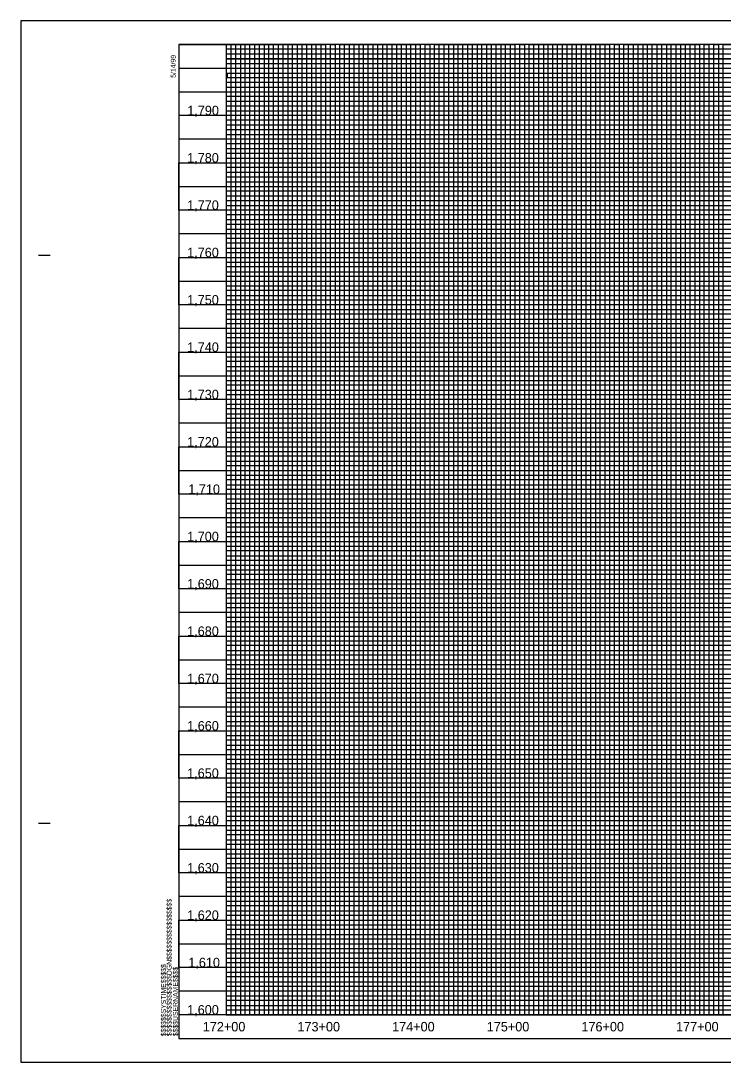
# Model space of a CAD drawing. Extents: x 505602 to 507286, y 483109 to 484209.
# Drawn here: x 505602 to 506344, y 483109 to 484209 of the extents above; entities that cross this region are included whole.
import ezdxf

# ---------------------------------------------------------------- set-up
doc = ezdxf.new("R2010")
doc.units = 0
for name, color, linetype in [('Exist Vertical Profile Vertical Axis Label', 7, 'Continuous'), ('Sheet Layout Profile Border Port 1', 7, 'Continuous'), ('Sheet Plot Border Outside CELL', 7, 'Continuous'), ('Sheet Profile CELL', 7, 'Continuous'), ('Sheet Profile Grid Major CELL', 7, 'Continuous'), ('Sheet Profile Grid Middle CELL', 7, 'Continuous'), ('Sheet Profile Grid Minor CELL', 7, 'Continuous')]:
    doc.layers.add(name, color=color, linetype=linetype)

msp = doc.modelspace()

# ---------------------------------------------------------------- linework, layer by layer
at = {"layer": 'Sheet Layout Profile Border Port 1'}
msp.add_lwpolyline([(505819.1, 484183.7), (505819.1, 483158.7), (507219.1, 483158.7), (507219.1, 484022.7), (507069, 484022.7), (507069, 484183.7)], close=True, dxfattribs=at)
at = {"layer": 'Sheet Plot Border Outside CELL'}
msp.add_lwpolyline([(507286.1, 484208.7), (505602.1, 484208.7), (505602.1, 483108.7), (507286.1, 483108.7)], close=True, dxfattribs=at)
at = {"layer": 'Sheet Profile CELL'}
for p, q in [((505620.6, 483961.2), (505633.1, 483961.2)), ((505620.6, 483361.2), (505633.1, 483361.2)), ((507269.1, 483158.7), (505769.1, 483158.7)), ((505769.1, 483133.7), (505769.1, 483133.7)), ((505769.1, 483133.7), (505769.1, 483133.7)), ((505769.1, 483133.7), (505769.1, 483133.7)), ((505769.1, 483133.7), (505769.1, 483133.7)), ((505769.1, 483133.7), (505769.1, 483133.7)), ((505769.1, 483133.7), (505769.1, 483133.7))]:
    msp.add_line(p, q, dxfattribs=at)
msp.add_lwpolyline([(507269.1, 484183.7), (505769.1, 484183.7), (505769.1, 483133.7), (507269.1, 483133.7)], close=True, dxfattribs=at)
msp.add_lwpolyline([(505806.6, 483133.7), (505806.6, 483133.7)], dxfattribs=at)
msp.add_lwpolyline([(505806.6, 483133.7), (505806.6, 483133.7)], dxfattribs=at)
at = {"layer": 'Sheet Profile Grid Major CELL'}
for points in [[(505769.1, 484183.7), (505819.1, 484183.7), (505819.1, 483158.7), (505869.1, 483158.7), (505869.1, 484183.7), (505919.1, 484183.7), (505919.1, 483158.7), (505969.1, 483158.7), (505969.1, 484183.7), (506019.1, 484183.7), (506019.1, 483158.7), (506069.1, 483158.7), (506069.1, 484183.7), (506119.1, 484183.7), (506119.1, 483158.7), (506169.1, 483158.7), (506169.1, 484183.7), (506219.1, 484183.7), (506219.1, 483158.7), (506269.1, 483158.7), (506269.1, 484183.7), (506319.1, 484183.7), (506319.1, 483158.7), (506369.1, 483158.7)], [(507069, 484108.7), (505769.2, 484108.7), (505769.2, 484158.7), (507069, 484158.7)], [(507269.1, 484008.7), (505769.1, 484008.7), (505769.1, 484058.7), (507069, 484058.7)], [(507269.1, 483908.7), (505769.1, 483908.7), (505769.1, 483958.7), (507269.1, 483958.7)], [(507269.1, 483808.7), (505769.1, 483808.7), (505769.1, 483858.7), (507269.1, 483858.7)], [(507269.1, 483708.7), (505769.1, 483708.7), (505769.1, 483758.7), (507269.1, 483758.7)], [(507269.1, 483608.7), (505769.1, 483608.7), (505769.1, 483658.7), (507269.1, 483658.7)], [(507269.1, 483508.7), (505769.1, 483508.7), (505769.1, 483558.7), (507269.1, 483558.7)], [(507269.1, 483408.7), (505769.1, 483408.7), (505769.1, 483458.7), (507269.1, 483458.7)], [(507269.1, 483308.7), (505769.1, 483308.7), (505769.1, 483358.7), (507269.1, 483358.7)], [(507269.1, 483208.7), (505769.1, 483208.7), (505769.1, 483258.7), (507269.1, 483258.7)]]:
    msp.add_lwpolyline(points, dxfattribs=at)
at = {"layer": 'Sheet Profile Grid Middle CELL'}
for points in [[(505844.1, 483158.7), (505844.1, 484183.7), (505894.1, 484183.7), (505894.1, 483158.7), (505944.1, 483158.7), (505944.1, 484183.7), (505994.1, 484183.7), (505994.1, 483158.7), (506044.1, 483158.7), (506044.1, 484183.7), (506094.1, 484183.7), (506094.1, 483158.7), (506144.1, 483158.7), (506144.1, 484183.7), (506194.1, 484183.7), (506194.1, 483158.7), (506244.1, 483158.7), (506244.1, 484183.7), (506294.1, 484183.7), (506294.1, 483158.7), (506344.1, 483158.7), (506344.1, 484183.7), (506394.1, 484183.7)], [(505769.1, 484133.7), (507069, 484133.7)], [(507069, 484083.7), (505769.1, 484083.7), (505769.1, 484033.7), (507069, 484033.7)], [(507269.1, 483983.7), (505769.1, 483983.7), (505769.1, 483933.7), (507269.1, 483933.7)], [(507269.1, 483883.7), (505769.1, 483883.7), (505769.1, 483833.7), (507269.1, 483833.7)], [(507269.1, 483783.7), (505769.1, 483783.7), (505769.1, 483733.7), (507269.1, 483733.7)], [(507269.1, 483683.7), (505769.1, 483683.7), (505769.1, 483633.7), (507269.1, 483633.7)], [(507269.1, 483583.7), (505769.1, 483583.7), (505769.1, 483533.7), (507269.1, 483533.7)], [(507269.1, 483483.7), (505769.1, 483483.7), (505769.1, 483433.7), (507269.1, 483433.7)], [(507269.1, 483383.7), (505769.1, 483383.7), (505769.1, 483333.7), (507269.1, 483333.7)], [(507269.1, 483283.7), (505769.1, 483283.7), (505769.1, 483233.7), (507269.1, 483233.7)], [(507269.1, 483183.7), (505769.1, 483183.7)]]:
    msp.add_lwpolyline(points, dxfattribs=at)
at = {"layer": 'Sheet Profile Grid Minor CELL'}
for p, q in [((505819.1, 484168.7), (507069.1, 484168.7)), ((507219.1, 484003.7), (505819.1, 484003.7)), ((505819.1, 484003.7), (505819.1, 483998.7)), ((505819.1, 483998.7), (507219.1, 483998.7)), ((507219.1, 483978.7), (505819.1, 483978.7))]:
    msp.add_line(p, q, dxfattribs=at)
for points in [[(505824.1, 484183.7), (505829.1, 484183.7), (505834.1, 484183.7), (505839.1, 484183.7), (505849.1, 484183.7), (505816, 484183.7), (505821, 484183.7), (505779.1, 484183.7), (505784.1, 484183.7), (505789.1, 484183.7), (505799.1, 484183.7), (505804.1, 484183.7), (505809.1, 484183.7), (505814.1, 484183.7), (505824.1, 484183.7), (505824.1, 483158.7), (505829.1, 483158.7), (505829.1, 484183.7), (505834.1, 484183.7), (505834.1, 483158.7), (505839.1, 483158.7), (505839.1, 484183.7), (505849.1, 484183.7), (505849.1, 483158.7), (505854.1, 483158.7), (505854.1, 484183.7), (505859.1, 484183.7), (505859.1, 483158.7), (505864.1, 483158.7), (505864.1, 484183.7), (505874.1, 484183.7), (505874.1, 483158.7), (505879.1, 483158.7), (505879.1, 484183.7), (505884.1, 484183.7), (505884.1, 483158.7), (505889.1, 483158.7), (505889.1, 484183.7), (505899.1, 484183.7), (505899.1, 483158.7), (505904.1, 483158.7), (505904.1, 484183.7), (505909.1, 484183.7), (505909.1, 483158.7), (505914.1, 483158.7), (505914.1, 484183.7), (505924.1, 484183.7), (505924.1, 483158.7), (505929.1, 483158.7), (505929.1, 484183.7), (505934.1, 484183.7), (505934.1, 483158.7), (505939.1, 483158.7), (505939.1, 484183.7), (505949.1, 484183.7), (505949.1, 483158.7), (505954.1, 483158.7), (505954.1, 484183.7), (505959.1, 484183.7), (505959.1, 483158.7), (505964.1, 483158.7), (505964.1, 484183.7), (505974.1, 484183.7), (505974.1, 483158.7), (505979.1, 483158.7), (505979.1, 484183.7), (505984.1, 484183.7), (505984.1, 483158.7)], [(507069, 484178.7), (505819.1, 484178.7), (505819.1, 484173.7), (507069, 484173.7)], [(505984.1, 483158.7), (505989.1, 483158.7), (505989.1, 484183.7), (505999.1, 484183.7), (505999.1, 483158.7), (506004.1, 483158.7), (506004.1, 484183.7), (506009.1, 484183.7), (506009.1, 483158.7), (506014.1, 483158.7), (506014.1, 484183.7), (506024.1, 484183.7), (506024.1, 483158.7), (506029.1, 483158.7), (506029.1, 484183.7), (506029.1, 484183.7), (506034.1, 484183.7), (506034.1, 483158.7), (506039.1, 483158.7), (506039.1, 484183.7), (506049.1, 484183.7), (506049.1, 483158.7), (506054.1, 483158.7), (506054.1, 484183.7), (506059.1, 484183.7), (506059.1, 483158.7), (506064.1, 483158.7), (506064.1, 484183.7), (506074.1, 484183.7), (506074.1, 483158.7), (506079.1, 483158.7), (506079.1, 484183.7), (506084.1, 484183.7), (506084.1, 483158.7), (506089.1, 483158.7), (506089.1, 484183.7), (506099.1, 484183.7), (506099.1, 483158.7), (506104.1, 483158.7), (506104.1, 484183.7), (506109.1, 484183.7), (506109.1, 483158.7), (506114.1, 483158.7), (506114.1, 484183.7), (506124.1, 484183.7), (506124.1, 483158.7), (506129.1, 483158.7), (506129.1, 484183.7), (506134.1, 484183.7), (506134.1, 483158.7), (506139.1, 483158.7), (506139.1, 484183.7), (506149.1, 484183.7), (506149.1, 483158.7), (506164.1, 483158.7), (506164.1, 484183.7), (506174.1, 484183.7), (506174.1, 483158.7), (506179.1, 483158.7), (506179.1, 484183.7), (506184.1, 484183.7), (506184.1, 483158.7), (506189.1, 483158.7), (506189.1, 484183.7), (506199.1, 484183.7), (506199.1, 483158.7), (506204.1, 483158.7), (506204.1, 484183.7), (506209.1, 484183.7), (506209.1, 483158.7), (506214.1, 483158.7), (506214.1, 484183.7), (506224.1, 484183.7), (506224.1, 483158.7), (506229.1, 483158.7), (506229.1, 484183.7), (506234.1, 484183.7), (506234.1, 483158.7), (506239.1, 483158.7), (506239.1, 484183.7), (506249.1, 484183.7), (506249.1, 483158.7), (506254.1, 483158.7), (506254.1, 484183.7), (506259.1, 484183.7), (506259.1, 483158.7), (506264.1, 483158.7), (506264.1, 484183.7), (506274.1, 484183.7), (506274.1, 483158.7), (506279.1, 483158.7), (506279.1, 484183.7), (506284.1, 484183.7), (506284.1, 483158.7), (506289.1, 483158.7), (506289.1, 484183.7), (506299.1, 484183.7), (506299.1, 483158.7)], [(506154.1, 484183.7), (506154.1, 483158.7), (506159.1, 483158.7), (506159.1, 484183.7)], [(506154.1, 484183.1), (506154.1, 483158.7), (506159.1, 483158.7), (506159.1, 484183.1)], [(506304.1, 484183.7), (506304.1, 483158.7), (506309.1, 483158.7), (506309.1, 484183.7), (506314.1, 484183.7), (506314.1, 483158.7), (506324.1, 483158.7), (506324.1, 484183.7), (506329.1, 484183.7), (506329.1, 483158.7), (506334.1, 483158.7), (506334.1, 484183.7), (506339.1, 484183.7), (506339.1, 483158.7)], [(507069, 484168.7), (505819.1, 484168.7), (505819.1, 484163.7), (507069, 484163.7)], [(507069, 484143.7), (505819.1, 484143.7), (505819.1, 484138.7), (507069, 484138.7)], [(507069, 484153), (505820.1, 484153), (505820.1, 484148.7), (507069, 484148.7)], [(507069, 484128.7), (505819.1, 484128.7), (505819.1, 484123.7), (507069, 484123.7)], [(507069, 484118.7), (505819.1, 484118.7), (505819.1, 484113.7), (507069, 484113.7)], [(507069, 484103.7), (505819.1, 484103.7), (505819.1, 484098.7), (507069, 484098.7)], [(507069, 484093.7), (505819.1, 484093.7), (505819.1, 484088.7), (507069, 484088.7)], [(507069, 484078.7), (505819.1, 484078.7), (505819.1, 484073.7), (507069, 484073.7)], [(507069, 484068.7), (505819.1, 484068.7), (505819.1, 484063.7), (507069, 484063.7)], [(507069, 484053.7), (505819.1, 484053.7), (505819.1, 484048.7), (507069, 484048.7)], [(507069, 484043.7), (505819.1, 484043.7), (505819.1, 484043.7), (505819.1, 484023.7), (507069, 484023.7)], [(505819.1, 484038.7), (507069, 484038.7)], [(507069, 484028.7), (505819.1, 484028.7)], [(507219.1, 484018.7), (505819.1, 484018.7), (505819.1, 484013.7), (507219.1, 484013.7)], [(507219.1, 483993.7), (505819.1, 483993.7), (505819.1, 483988.7), (507219.1, 483988.7)], [(507219.1, 483973.7), (505819.1, 483973.7), (505819.1, 483968.7), (507219.1, 483968.7)], [(507219.1, 483963.7), (505819.1, 483963.7)], [(505819.1, 483953.7), (507219.1, 483953.7)], [(507219.1, 483948.7), (505819.1, 483948.7), (505819.1, 483943.7), (507219.1, 483943.7)], [(507219.1, 483938.7), (505819.1, 483938.7), (505819.1, 483928.7), (507219.1, 483928.7)], [(507219.1, 483923.7), (505819.1, 483923.7), (505819.1, 483918.7), (507219.1, 483918.7)], [(507219.1, 483913.7), (505819.1, 483913.7), (505819.1, 483903.7), (507219.1, 483903.7)], [(507219.1, 483898.7), (505819.1, 483898.7), (505819.1, 483893.7), (507219.1, 483893.7)], [(507219.1, 483888.7), (505819.1, 483888.7), (505819.1, 483878.7), (507219.1, 483878.7)], [(507219.1, 483873.7), (505819.1, 483873.7), (505819.1, 483868.7), (507219.1, 483868.7)], [(507219.1, 483863.7), (505819.1, 483863.7), (505819.1, 483853.7), (507219.1, 483853.7)], [(507219.1, 483848.7), (505819.1, 483848.7), (505819.1, 483843.7), (507219.1, 483843.7)], [(507219.1, 483838.7), (505819.1, 483838.7), (505819.1, 483828.7), (507219.1, 483828.7)], [(507219.1, 483823.7), (505819.1, 483823.7), (505819.1, 483818.7), (507219.1, 483818.7)], [(507219.1, 483813.7), (505819.1, 483813.7), (505819.1, 483803.7), (507219.1, 483803.7)], [(507219.1, 483798.7), (505819.1, 483798.7), (505819.1, 483793.7), (507219.1, 483793.7)], [(507219.1, 483788.7), (505819.1, 483788.7), (505819.1, 483778.7), (507219.1, 483778.7)], [(507219.1, 483773.7), (505819.1, 483773.7), (505819.1, 483768.7), (507219.1, 483768.7)], [(507219.1, 483763.7), (505819.1, 483763.7), (505819.1, 483753.7), (507219.1, 483753.7)], [(507219.1, 483748.7), (505819.1, 483748.7), (505819.1, 483743.7), (507219.1, 483743.7)], [(507219.1, 483738.7), (505819.1, 483738.7), (505819.1, 483728.7), (507219.1, 483728.7)], [(507219.1, 483723.7), (505819.1, 483723.7), (505819.1, 483718.7), (507219.1, 483718.7)], [(507219.1, 483713.7), (505819.1, 483713.7), (505819.1, 483703.7), (507219.1, 483703.7)], [(507219.1, 483698.7), (505819.1, 483698.7), (505819.1, 483693.7), (507219.1, 483693.7)], [(507219.1, 483688.7), (505819.1, 483688.7), (505819.1, 483678.7), (507219.1, 483678.7)], [(507219.1, 483673.7), (505819.1, 483673.7), (505819.1, 483668.7), (507219.1, 483668.7)], [(507219.1, 483663.7), (505819.1, 483663.7)], [(505819.1, 483653.7), (507219.1, 483653.7)], [(507219.1, 483648.7), (505819.1, 483648.7), (505819.1, 483643.7), (507219.1, 483643.7)], [(507219.1, 483638.7), (505819.1, 483638.7), (505819.1, 483628.7), (507219.1, 483628.7)], [(507219.1, 483623.7), (505819.1, 483623.7), (505819.1, 483618.7), (507219.1, 483618.7)], [(507219.1, 483613.7), (505819.1, 483613.7), (505819.1, 483603.7), (507219.1, 483603.7)], [(507219.1, 483598.7), (505819.1, 483598.7), (505819.1, 483593.7), (507219.1, 483593.7)], [(507219.1, 483588.7), (505819.1, 483588.7), (505819.1, 483578.7), (507219.1, 483578.7)], [(507219.1, 483573.7), (505819.1, 483573.7), (505819.1, 483568.7), (507219.1, 483568.7)], [(507219.1, 483563.7), (505819.1, 483563.7), (505819.1, 483553.7), (507219.1, 483553.7)], [(507219.1, 483548.7), (505819.1, 483548.7), (505819.1, 483543.7), (507219.1, 483543.7)], [(507219.1, 483538.7), (505819.1, 483538.7), (505819.1, 483528.7), (507219.1, 483528.7)], [(507219.1, 483523.7), (505819.1, 483523.7), (505819.1, 483518.7), (507219.1, 483518.7)], [(507219.1, 483513.7), (505819.1, 483513.7), (505819.1, 483503.7), (507219.1, 483503.7)], [(507219.1, 483498.7), (505819.1, 483498.7), (505819.1, 483493.7), (507219.1, 483493.7)], [(507219.1, 483488.7), (505819.1, 483488.7), (505819.1, 483478.7), (507219.1, 483478.7)], [(507219.1, 483473.7), (505819.1, 483473.7), (505819.1, 483468.7), (507219.1, 483468.7)], [(507219.1, 483463.7), (505819.1, 483463.7), (505819.1, 483453.7), (507219.1, 483453.7)], [(507219.1, 483448.7), (505819.1, 483448.7), (505819.1, 483443.7), (507219.1, 483443.7)], [(507219.1, 483438.7), (505819.1, 483438.7), (505819.1, 483428.7), (507219.1, 483428.7)], [(507219.1, 483423.7), (505819.1, 483423.7), (505819.1, 483418.7), (507219.1, 483418.7)], [(507219.1, 483413.7), (505819.1, 483413.7), (505819.1, 483403.7), (507219.1, 483403.7)], [(507219.1, 483398.7), (505819.1, 483398.7), (505819.1, 483393.7), (507219.1, 483393.7)], [(507219.1, 483388.7), (505819.1, 483388.7), (505819.1, 483378.7), (507219.1, 483378.7)], [(507219.1, 483373.7), (505819.1, 483373.7), (505819.1, 483368.7), (507219.1, 483368.7)], [(507219.1, 483363.7), (505819.1, 483363.7)], [(505819.1, 483353.7), (507219.1, 483353.7)], [(507219.1, 483348.7), (505819.1, 483348.7), (505819.1, 483343.7), (507219.1, 483343.7)], [(507219.1, 483338.7), (505819.1, 483338.7)], [(505819.1, 483328.7), (507219.1, 483328.7)], [(507219.1, 483323.7), (505819.1, 483323.7), (505819.1, 483318.7), (507219.1, 483318.7)], [(507219.1, 483313.7), (505819.1, 483313.7), (505819.1, 483303.7), (507219.1, 483303.7)], [(507219.1, 483298.7), (505819.1, 483298.7), (505819.1, 483293.7), (507219.1, 483293.7)], [(507219.1, 483288.7), (505819.1, 483288.7), (505819.1, 483278.7), (507219.1, 483278.7)], [(507219.1, 483273.7), (505819.1, 483273.7), (505819.1, 483268.7), (507219.1, 483268.7)], [(507219.1, 483263.7), (505819.1, 483263.7), (505819.1, 483253.7), (507219.1, 483253.7)], [(507219.1, 483248.7), (505819.1, 483248.7), (505819.1, 483243.7), (507219.1, 483243.7)], [(507219.1, 483238.7), (505819.1, 483238.7), (505819.1, 483228.7), (507219.1, 483228.7)], [(507219.1, 483223.7), (505819.1, 483223.7), (505819.1, 483218.7), (507219.1, 483218.7)], [(507219.1, 483213.7), (505819.1, 483213.7), (505819.1, 483203.7), (507219.1, 483203.7)], [(507219.1, 483198.7), (505819.1, 483198.7), (505819.1, 483193.7), (507219.1, 483193.7)], [(507219.1, 483188.7), (505819.1, 483188.7), (505819.1, 483178.7), (507219.1, 483178.7)], [(507219.1, 483173.7), (505819.1, 483173.7), (505819.1, 483168.7), (507219.1, 483168.7)], [(507219.1, 483163.7), (505819.1, 483163.7)]]:
    msp.add_lwpolyline(points, dxfattribs=at)

# ---------------------------------------------------------------- texts
at = {"layer": 'Exist Vertical Profile Vertical Axis Label'}
for s, p in [('1,790', (505777.9, 484109)), ('1,780', (505777.8, 484059)), ('1,770', (505777.8, 484009)), ('1,760', (505777.8, 483959)), ('1,750', (505777.8, 483909)), ('1,740', (505777.8, 483859)), ('1,730', (505777.8, 483809)), ('1,720', (505777.8, 483759)), ('1,710', (505779, 483709)), ('1,700', (505777.8, 483659)), ('1,690', (505777.8, 483609)), ('1,680', (505777.8, 483559)), ('1,670', (505777.8, 483509)), ('1,660', (505777.8, 483459)), ('1,650', (505777.8, 483409)), ('1,640', (505777.8, 483359)), ('1,630', (505777.8, 483309)), ('1,620', (505777.8, 483259)), ('1,610', (505779, 483209)), ('1,600', (505777.8, 483159)), ('172+00', (505794.3, 483141.2)), ('173+00', (505894.3, 483141.2)), ('174+00', (505994.3, 483141.2)), ('175+00', (506094.3, 483141.2)), ('176+00', (506194.3, 483141.2)), ('177+00', (506294.3, 483141.2))]:
    msp.add_text(s, height=10, dxfattribs=at).set_placement(p)
at = {"layer": 'Sheet Profile CELL'}
for s, p in [('5/14/99', (505765.8, 484148.5)), ('$$$$$$$$$$$$$$$$DGN$$$$$$$$$$$$$$$$', (505761.4, 483136.1)), ('$$$$$$SYSTIME$$$$$', (505755.4, 483136.1)), ('$$$$USERNAME$$$$', (505768, 483136.1))]:
    msp.add_text(s, height=5.25, rotation=90, dxfattribs=at).set_placement(p)

doc.saveas('drawing.dxf')
